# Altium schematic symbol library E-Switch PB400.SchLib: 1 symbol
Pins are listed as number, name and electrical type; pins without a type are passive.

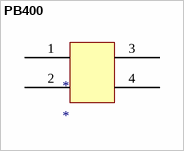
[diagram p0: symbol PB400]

## PB400
designator *
footprint PB400
pins: 1, 2, 3, 4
